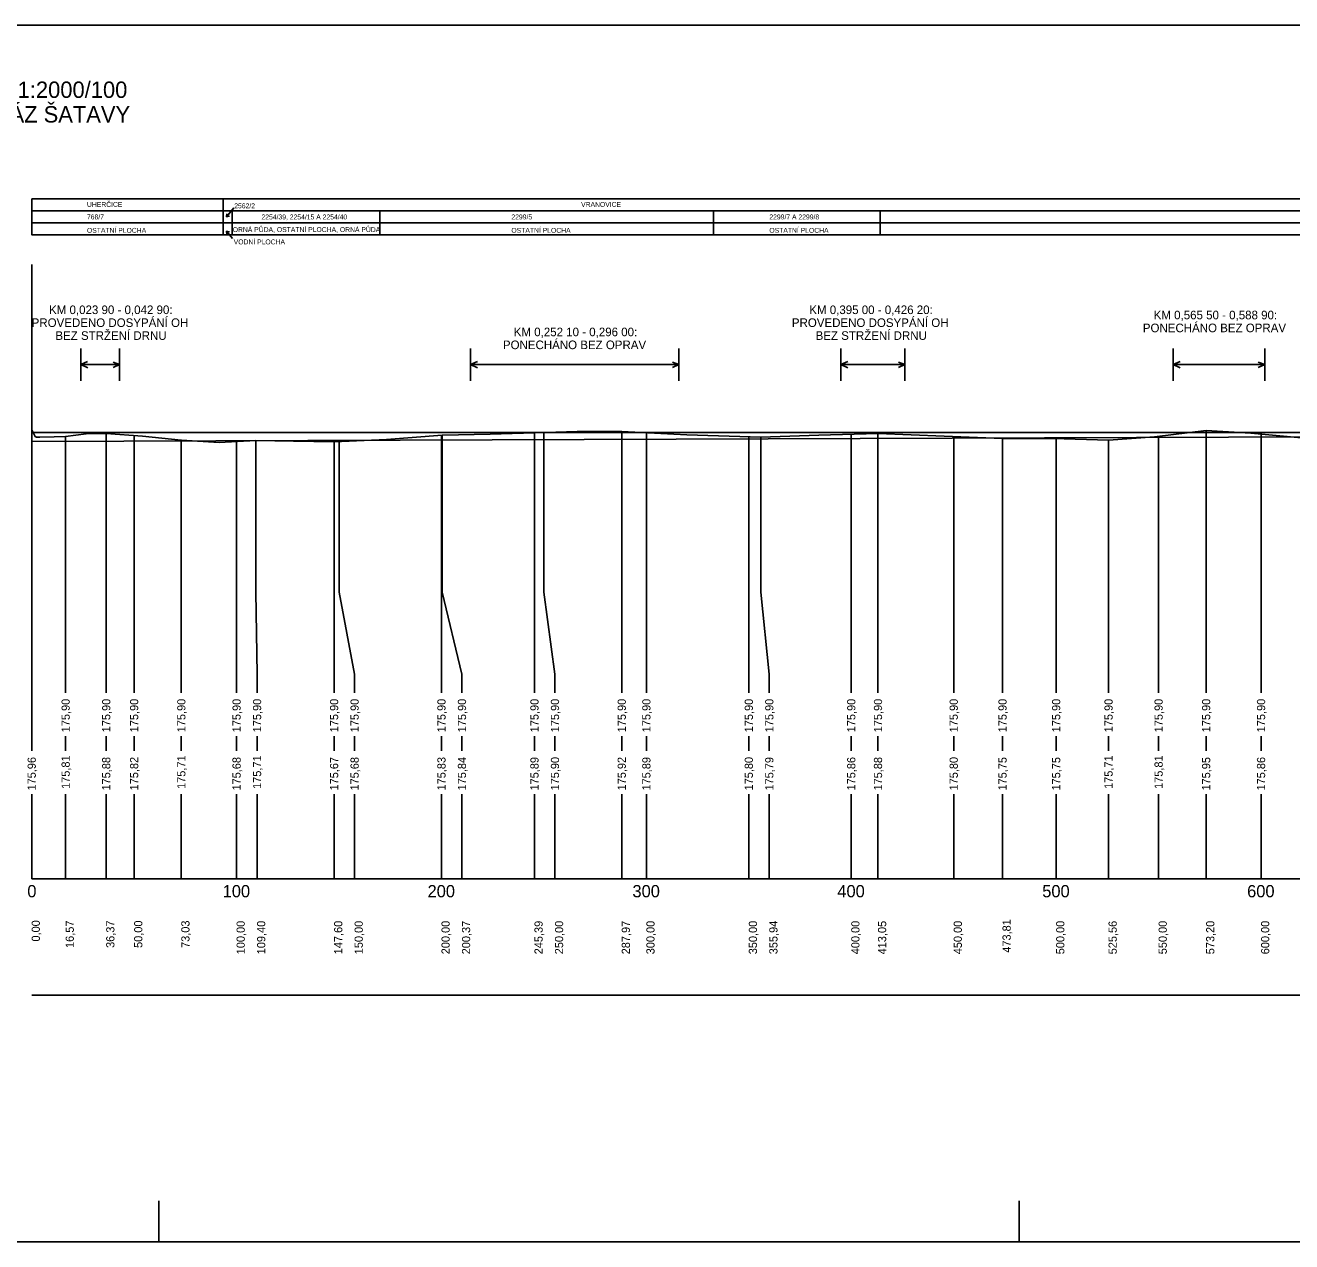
# Model space of a CAD drawing. Extents: x -614174 to -599765, y -1185887 to -1181080.
# Drawn here: x -613518 to -612900, y -1183382 to -1182788 of the extents above; entities that cross this region are included whole.
import ezdxf

# ---------------------------------------------------------------- set-up
doc = ezdxf.new("R2010")
doc.units = 0
for name, color, linetype in [('11', 7, 'Continuous'), ('13', 7, 'Continuous'), ('4', 7, 'Continuous'), ('56', 7, 'Continuous'), ('návrh', 7, 'Continuous')]:
    doc.layers.add(name, color=color, linetype=linetype)

msp = doc.modelspace()

# ---------------------------------------------------------------- linework, layer by layer
msp.add_line((-613514.51, -1182987.26), (-611402.58, -1182987.26))
for points in [[(-613514.51, -1182986.05), (-613512.8, -1182989.24), (-613512.09, -1182989.61), (-613510.49, -1182989.54), (-613503.56, -1182989.41), (-613497.94, -1182989.15), (-613497.94, -1182989.15), (-613487.99, -1182987.95), (-613478.19, -1182987.75), (-613478.13, -1182987.75), (-613460.41, -1182989.13), (-613441.48, -1182991.09), (-613441.47, -1182991.09), (-613422.98, -1182992.16), (-613405.11, -1182991.14), (-613405.05, -1182991.14), (-613386.8, -1182991.58), (-613366.94, -1182991.84), (-613366.91, -1182991.84), (-613341.38, -1182990.75), (-613314.13, -1182988.55), (-613313.99, -1182988.54), (-613290.74, -1182988.06), (-613269.13, -1182987.45), (-613269.12, -1182987.45), (-613248.3, -1182986.86), (-613226.53, -1182986.86), (-613226.48, -1182986.86), (-613194.77, -1182988.45), (-613158.58, -1182989.53), (-613158.57, -1182989.53), (-613130.4, -1182988.56), (-613101.46, -1182987.75), (-613101.45, -1182987.75), (-613069.19, -1182989), (-613040.69, -1182990.25), (-613040.67, -1182990.25), (-613016.03, -1182990.13), (-612988.94, -1182990.96), (-612988.91, -1182990.96), (-612966.58, -1182989.37), (-612941.36, -1182986.33), (-612941.31, -1182986.34), (-612919.57, -1182987.61), (-612894.76, -1182989.95)], [(-613514.51, -1182986.05), (-613514.51, -1183065.26), (-613514.51, -1183105.26), (-613514.51, -1183114.34)], [(-613226.53, -1182986.86), (-613226.53, -1183065.26), (-613226.53, -1183105.26), (-613226.53, -1183114.34)], [(-612941.31, -1182986.34), (-612941.31, -1183065.26), (-612941.31, -1183105.26), (-612941.31, -1183114.34)], [(-613497.94, -1182989.15), (-613497.94, -1183065.26), (-613497.94, -1183105.26), (-613497.94, -1183114.34)], [(-613478.13, -1182987.75), (-613478.13, -1183065.26), (-613478.13, -1183105.26), (-613478.13, -1183114.34)], [(-613464.51, -1182988.81), (-613464.51, -1183065.26), (-613464.51, -1183105.26), (-613464.51, -1183114.34)], [(-613441.48, -1182991.09), (-613441.48, -1183065.26), (-613441.48, -1183105.26), (-613441.48, -1183114.34)], [(-613414.51, -1182991.68), (-613414.51, -1183065.26), (-613414.51, -1183105.26), (-613414.51, -1183114.34)], [(-613405.11, -1182991.14), (-613405.11, -1183065.26), (-613404.51, -1183105.26), (-613404.51, -1183114.34)], [(-613366.91, -1182991.84), (-613366.91, -1183065.26), (-613366.91, -1183105.26), (-613366.91, -1183114.34)], [(-613364.51, -1182991.74), (-613364.51, -1183065.26), (-613356.91, -1183105.26), (-613356.91, -1183114.34)], [(-613314.51, -1182988.58), (-613314.51, -1183065.26), (-613314.51, -1183105.26), (-613314.51, -1183114.34)], [(-613314.13, -1182988.55), (-613314.13, -1183065.26), (-613304.51, -1183105.26), (-613304.51, -1183114.34)], [(-613269.12, -1182987.45), (-613269.12, -1183065.26), (-613269.12, -1183105.26), (-613269.12, -1183114.34)], [(-613264.51, -1182987.32), (-613264.51, -1183065.26), (-613259.12, -1183105.26), (-613259.12, -1183114.34)], [(-613214.51, -1182987.46), (-613214.51, -1183065.26), (-613214.51, -1183105.26), (-613214.51, -1183114.34)], [(-613164.51, -1182989.36), (-613164.51, -1183065.26), (-613164.51, -1183105.26), (-613164.51, -1183114.34)], [(-613158.57, -1182989.53), (-613158.57, -1183065.26), (-613154.51, -1183105.26), (-613154.51, -1183114.34)], [(-613114.51, -1182988.12), (-613114.51, -1183065.26), (-613114.51, -1183105.26), (-613114.51, -1183114.34)], [(-613101.46, -1182987.75), (-613101.46, -1183065.26), (-613101.46, -1183105.26), (-613101.46, -1183114.34)], [(-613064.51, -1182989.2), (-613064.51, -1183065.26), (-613064.51, -1183105.26), (-613064.51, -1183114.34)], [(-613040.69, -1182990.25), (-613040.69, -1183065.26), (-613040.69, -1183105.26), (-613040.69, -1183114.34)], [(-613014.51, -1182990.18), (-613014.51, -1183065.26), (-613014.51, -1183105.26), (-613014.51, -1183114.34)], [(-612988.94, -1182990.96), (-612988.94, -1183065.26), (-612988.94, -1183105.26), (-612988.94, -1183114.34)], [(-612964.51, -1182989.12), (-612964.51, -1183065.26), (-612964.51, -1183105.26), (-612964.51, -1183114.34)], [(-612914.51, -1182988.09), (-612914.51, -1183065.26), (-612914.51, -1183105.26), (-612914.51, -1183114.34)], [(-613497.94, -1183135.54), (-613497.94, -1183142.7)], [(-613478.13, -1183135.54), (-613478.13, -1183142.7)], [(-613464.51, -1183135.54), (-613464.51, -1183142.7)], [(-613441.48, -1183135.54), (-613441.48, -1183142.7)], [(-613414.51, -1183135.54), (-613414.51, -1183142.7)], [(-613404.51, -1183135.54), (-613404.51, -1183142.7)], [(-613366.91, -1183135.54), (-613366.91, -1183142.7)], [(-613356.91, -1183135.54), (-613356.91, -1183142.7)], [(-613314.51, -1183135.54), (-613314.51, -1183142.7)], [(-613304.51, -1183135.54), (-613304.51, -1183142.7)], [(-613269.12, -1183135.54), (-613269.12, -1183142.7)], [(-613259.12, -1183135.54), (-613259.12, -1183142.7)], [(-613226.53, -1183135.54), (-613226.53, -1183142.7)], [(-613214.51, -1183135.54), (-613214.51, -1183142.7)], [(-613164.51, -1183135.54), (-613164.51, -1183142.7)], [(-613154.51, -1183135.54), (-613154.51, -1183142.7)], [(-613114.51, -1183135.54), (-613114.51, -1183142.7)], [(-613101.46, -1183135.54), (-613101.46, -1183142.7)], [(-613064.51, -1183135.54), (-613064.51, -1183142.7)], [(-613040.69, -1183135.54), (-613040.69, -1183142.7)], [(-613014.51, -1183135.54), (-613014.51, -1183142.7)], [(-612988.94, -1183135.54), (-612988.94, -1183142.7)], [(-612964.51, -1183135.54), (-612964.51, -1183142.7)], [(-612941.31, -1183135.54), (-612941.31, -1183142.7)], [(-612914.51, -1183135.54), (-612914.51, -1183142.7)], [(-613497.94, -1183163.91), (-613497.94, -1183205.26)], [(-613478.13, -1183163.91), (-613478.13, -1183205.26)], [(-613464.51, -1183163.91), (-613464.51, -1183205.26)], [(-613441.48, -1183163.91), (-613441.48, -1183205.26)], [(-613414.51, -1183163.91), (-613414.51, -1183205.26)], [(-613404.51, -1183163.91), (-613404.51, -1183205.26)], [(-613366.91, -1183163.91), (-613366.91, -1183205.26)], [(-613356.91, -1183163.91), (-613356.91, -1183205.26)], [(-613314.51, -1183163.91), (-613314.51, -1183205.26)], [(-613304.51, -1183163.91), (-613304.51, -1183205.26)], [(-613269.12, -1183163.91), (-613269.12, -1183205.26)], [(-613259.12, -1183163.91), (-613259.12, -1183205.26)], [(-613226.53, -1183163.91), (-613226.53, -1183205.26)], [(-613214.51, -1183163.91), (-613214.51, -1183205.26)], [(-613164.51, -1183163.91), (-613164.51, -1183205.26)], [(-613154.51, -1183163.91), (-613154.51, -1183205.26)], [(-613114.51, -1183163.91), (-613114.51, -1183205.26)], [(-613101.46, -1183163.91), (-613101.46, -1183205.26)], [(-613064.51, -1183163.91), (-613064.51, -1183205.26)], [(-613040.69, -1183163.91), (-613040.69, -1183205.26)], [(-613014.51, -1183163.91), (-613014.51, -1183205.26)], [(-612988.94, -1183163.91), (-612988.94, -1183205.26)], [(-612964.51, -1183163.91), (-612964.51, -1183205.26)], [(-612941.31, -1183163.91), (-612941.31, -1183205.26)], [(-612914.51, -1183163.91), (-612914.51, -1183205.26)], [(-613514.51, -1183205.26), (-613514.51, -1183205.26)], [(-613514.51, -1183261.99), (-611395.59, -1183261.99)]]:
    msp.add_lwpolyline(points)
at = {"layer": '56'}
for p, q in [((-613514.51, -1183114.34), (-613514.51, -1182905.26)), ((-613514.51, -1183114.34), (-613514.51, -1183142.7)), ((-613514.51, -1183163.91), (-613514.51, -1183205.26)), ((-613514.51, -1183205.26), (-613514.51, -1183204.26)), ((-613514.51, -1183205.26), (-611314.51, -1183205.26)), ((-613414.51, -1183205.26), (-613414.51, -1183204.26)), ((-613314.51, -1183205.26), (-613314.51, -1183204.26)), ((-613214.51, -1183205.26), (-613214.51, -1183204.26)), ((-613114.51, -1183205.26), (-613114.51, -1183204.26)), ((-613014.51, -1183205.26), (-613014.51, -1183204.26)), ((-612914.51, -1183205.26), (-612914.51, -1183204.26))]:
    msp.add_line(p, q, dxfattribs=at)
at = {"layer": 'návrh'}
for p, q in [((-613657.4, -1182788.43), (-610932.51, -1182788.43)), ((-613421.01, -1182873.17), (-613421.01, -1182890.67)), ((-613415.79, -1182877.64), (-613419.48, -1182882.01)), ((-613419.48, -1182882.01), (-613419.29, -1182880.43)), ((-613419.48, -1182882.01), (-613417.95, -1182881.56)), ((-613416.71, -1182879), (-613416.71, -1182890.67)), ((-613344.61, -1182879), (-613344.61, -1182890.67)), ((-613181.71, -1182879), (-613181.71, -1182890.67)), ((-613100.41, -1182879), (-613100.41, -1182890.67)), ((-613416.43, -1182892.47), (-613419.48, -1182888.92)), ((-613419.48, -1182888.92), (-613417.95, -1182889.36)), ((-613419.48, -1182888.92), (-613419.28, -1182890.5)), ((-613490.57, -1182961.98), (-613490.57, -1182946.2)), ((-613471.61, -1182961.98), (-613471.61, -1182946.2)), ((-613300.36, -1182961.98), (-613300.36, -1182946.2)), ((-613198.62, -1182961.98), (-613198.62, -1182946.2)), ((-613119.53, -1182961.98), (-613119.53, -1182946.2)), ((-613088.33, -1182961.98), (-613088.33, -1182946.2)), ((-612957.33, -1182961.98), (-612957.33, -1182946.2)), ((-612912.7, -1182961.98), (-612912.7, -1182946.2)), ((-613490.57, -1182954.09), (-613487.21, -1182952.64)), ((-613490.57, -1182954.09), (-613471.61, -1182954.09)), ((-613490.57, -1182954.09), (-613487.17, -1182955.65)), ((-613471.61, -1182954.09), (-613474.8, -1182952.85)), ((-613471.61, -1182954.09), (-613474.8, -1182955.45)), ((-613300.36, -1182954.09), (-613296.99, -1182952.64)), ((-613300.36, -1182954.09), (-613296.96, -1182955.65)), ((-613300.36, -1182954.09), (-613198.62, -1182954.09)), ((-613198.62, -1182954.09), (-613201.8, -1182952.85)), ((-613198.62, -1182954.09), (-613201.8, -1182955.45)), ((-613119.53, -1182954.09), (-613116.16, -1182952.64)), ((-613119.53, -1182954.09), (-613116.13, -1182955.65)), ((-613119.53, -1182954.09), (-613088.33, -1182954.09)), ((-613088.33, -1182954.09), (-613091.51, -1182952.85)), ((-613088.33, -1182954.09), (-613091.51, -1182955.45)), ((-612957.33, -1182954.09), (-612953.96, -1182952.64)), ((-612957.33, -1182954.09), (-612953.92, -1182955.65)), ((-612957.33, -1182954.09), (-612912.7, -1182954.09)), ((-612912.7, -1182954.09), (-612915.88, -1182952.85)), ((-612912.7, -1182954.09), (-612915.88, -1182955.45)), ((-611394.51, -1182984.06), (-613514.51, -1182991.66)), ((-613452.51, -1183362.43), (-613452.51, -1183382.43)), ((-613032.51, -1183362.43), (-613032.51, -1183382.43)), ((-613452.51, -1183382.43), (-613657.4, -1183382.43)), ((-613452.51, -1183382.43), (-610932.51, -1183382.43))]:
    msp.add_line(p, q, dxfattribs=at)
for points in [[(-613514.51, -1182873.17), (-611398.36, -1182873.17), (-611398.36, -1182879), (-613514.51, -1182879)], [(-613514.51, -1182879), (-611398.36, -1182879), (-611398.36, -1182884.84), (-613514.51, -1182884.84)], [(-613514.51, -1182884.84), (-611398.36, -1182884.84), (-611398.36, -1182890.67), (-613514.51, -1182890.67)]]:
    msp.add_lwpolyline(points, close=True, dxfattribs=at)

# ---------------------------------------------------------------- texts
at = {"layer": '11'}
for s, height, rotation, p in [('175,90', 4, 90, (-613495.94, -1183133.67)), ('175,90', 4, 90, (-613476.13, -1183133.67)), ('175,90', 4, 90, (-613462.51, -1183133.67)), ('175,90', 4, 90, (-613439.48, -1183133.67)), ('175,90', 4, 90, (-613412.51, -1183133.67)), ('175,90', 4, 90, (-613402.51, -1183133.67)), ('175,90', 4, 90, (-613364.91, -1183133.67)), ('175,90', 4, 90, (-613354.91, -1183133.67)), ('175,90', 4, 90, (-613312.51, -1183133.67)), ('175,90', 4, 90, (-613302.51, -1183133.67)), ('175,90', 4, 90, (-613267.12, -1183133.67)), ('175,90', 4, 90, (-613257.12, -1183133.67)), ('175,90', 4, 90, (-613224.53, -1183133.67)), ('175,90', 4, 90, (-613212.51, -1183133.67)), ('175,90', 4, 90, (-613162.51, -1183133.67)), ('175,90', 4, 90, (-613152.51, -1183133.67)), ('175,90', 4, 90, (-613112.51, -1183133.67)), ('175,90', 4, 90, (-613099.46, -1183133.67)), ('175,90', 4, 90, (-613062.51, -1183133.67)), ('175,90', 4, 90, (-613038.69, -1183133.67)), ('175,90', 4, 90, (-613012.51, -1183133.67)), ('175,90', 4, 90, (-612986.94, -1183133.67)), ('175,90', 4, 90, (-612962.51, -1183133.67)), ('175,90', 4, 90, (-612939.31, -1183133.67)), ('175,90', 4, 90, (-612912.51, -1183133.67)), ('175,96', 4, 90, (-613512.51, -1183162.09)), ('175,81', 4, 90, (-613495.94, -1183161.32)), ('175,88', 4, 90, (-613476.13, -1183162.1)), ('175,82', 4, 90, (-613462.51, -1183162.05)), ('175,71', 4, 90, (-613439.48, -1183161.32)), ('175,68', 4, 90, (-613412.51, -1183162.1)), ('175,71', 4, 90, (-613402.51, -1183161.32)), ('175,67', 4, 90, (-613364.91, -1183162.09)), ('175,68', 4, 90, (-613354.91, -1183162.1)), ('175,83', 4, 90, (-613312.51, -1183162.09)), ('175,84', 4, 90, (-613302.51, -1183162.07)), ('175,89', 4, 90, (-613267.12, -1183162.1)), ('175,90', 4, 90, (-613257.12, -1183162.07)), ('175,92', 4, 90, (-613224.53, -1183162.05)), ('175,89', 4, 90, (-613212.51, -1183162.1)), ('175,80', 4, 90, (-613162.51, -1183162.07)), ('175,79', 4, 90, (-613152.51, -1183162.1)), ('175,86', 4, 90, (-613112.51, -1183162.09)), ('175,88', 4, 90, (-613099.46, -1183162.1)), ('175,80', 4, 90, (-613062.51, -1183162.07)), ('175,75', 4, 90, (-613038.69, -1183162.12)), ('175,75', 4, 90, (-613012.51, -1183162.12)), ('175,71', 4, 90, (-612986.94, -1183161.32)), ('175,81', 4, 90, (-612962.51, -1183161.32)), ('175,95', 4, 90, (-612939.31, -1183162.12)), ('175,86', 4, 90, (-612912.51, -1183162.09)), ('-', 6.000000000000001e-12, 53.1301, (-613514.51, -1183205.26)), ('0,00', 4, 90, (-613510.51, -1183235.86)), ('16,57', 4, 90, (-613493.94, -1183238.98)), ('36,37', 4, 90, (-613474.13, -1183238.98)), ('50,00', 4, 90, (-613460.51, -1183238.97)), ('73,03', 4, 90, (-613437.48, -1183238.98)), ('100,00', 4, 90, (-613410.51, -1183242.07)), ('109,40', 4, 90, (-613400.51, -1183242.07)), ('147,60', 4, 90, (-613362.91, -1183242.07)), ('150,00', 4, 90, (-613352.91, -1183242.07)), ('200,00', 4, 90, (-613310.51, -1183242.07)), ('200,37', 4, 90, (-613300.51, -1183242.09)), ('245,39', 4, 90, (-613265.12, -1183242.1)), ('250,00', 4, 90, (-613255.12, -1183242.07)), ('287,97', 4, 90, (-613222.53, -1183242.09)), ('300,00', 4, 90, (-613210.51, -1183242.07)), ('350,00', 4, 90, (-613160.51, -1183242.07)), ('355,94', 4, 90, (-613150.51, -1183242.07)), ('400,00', 4, 90, (-613110.51, -1183242.07)), ('413,05', 4, 90, (-613097.46, -1183242.12)), ('450,00', 4, 90, (-613060.51, -1183242.07)), ('473,81', 4, 90, (-613036.69, -1183241.32)), ('500,00', 4, 90, (-613010.51, -1183242.07)), ('525,56', 4, 90, (-612984.94, -1183242.09)), ('550,00', 4, 90, (-612960.51, -1183242.07)), ('573,20', 4, 90, (-612937.31, -1183242.07)), ('600,00', 4, 90, (-612910.51, -1183242.07))]:
    msp.add_text(s, height=height, rotation=rotation, dxfattribs=at).set_placement(p)
at = {"layer": '13'}
for s, height, p in [('UHERČICE', 2.4, (-613487.53, -1182877.11)), ('2562/2', 2.4, (-613415.65, -1182877.79)), ('VRANOVICE', 2.4, (-613246.36, -1182877.11)), ('768/7', 2.4, (-613487.53, -1182883.21)), ('2254/39, 2254/15 A 2254/40', 2.4, (-613402.36, -1182883.21)), ('2299/5', 2.4, (-613280.38, -1182883.21)), ('2299/7 A 2299/8', 2.4, (-613154.48, -1182883.21)), ('OSTATNÍ PLOCHA', 2.4, (-613487.53, -1182889.76)), ('ORNÁ PŮDA, OSTATNÍ PLOCHA, ORNÁ PŮDA', 2.4, (-613416.39, -1182889.38)), ('OSTATNÍ PLOCHA', 2.4, (-613280.38, -1182889.76)), ('OSTATNÍ PLOCHA', 2.4, (-613154.48, -1182889.76)), ('VODNÍ PLOCHA', 2.4, (-613415.91, -1182895.4)), ('PROVEDENO DOSYPÁNÍ OH', 4.2, (-613514.52, -1182935.74)), ('KM 0,023 90 - 0,042 90: ', 4.2, (-613506.02, -1182929.44)), ('PROVEDENO DOSYPÁNÍ OH', 4.2, (-613143.49, -1182935.74)), ('KM 0,395 00 - 0,426 20: ', 4.2, (-613134.99, -1182929.44)), ('KM 0,565 50 - 0,588 90: ', 4.2, (-612966.91, -1182932)), ('BEZ STRŽENÍ DRNU', 4.2, (-613502.94, -1182942.04)), ('KM 0,252 10 - 0,296 00: ', 4.2, (-613279.23, -1182940.27)), ('BEZ STRŽENÍ DRNU', 4.2, (-613131.91, -1182942.04)), ('PONECHÁNO BEZ OPRAV', 4.2, (-612972.2, -1182938.3)), ('PONECHÁNO BEZ OPRAV', 4.2, (-613284.52, -1182946.57)), ('0', 6, (-613516.64, -1183214.26)), ('100', 6, (-613421.3, -1183214.26)), ('200', 6, (-613321.3, -1183214.26)), ('300', 6, (-613221.3, -1183214.26)), ('400', 6, (-613121.3, -1183214.26)), ('500', 6, (-613021.3, -1183214.26)), ('600', 6, (-612921.3, -1183214.26))]:
    msp.add_text(s, height=height, dxfattribs=at).set_placement(p)
at = {"layer": '4'}
for s, p in [('PODÉLN Ý PROFIL 1:2000/100', (-613620.05, -1182823.89)), ('SO-03: HRÁZ ŠATAVY ', (-613577.63, -1182835.89))]:
    msp.add_text(s, height=8, dxfattribs=at).set_placement(p)

doc.saveas('drawing.dxf')
